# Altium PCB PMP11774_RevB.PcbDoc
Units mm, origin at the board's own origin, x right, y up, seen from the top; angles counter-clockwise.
Board outline 103.13 x 27 mm, 2 copper layers (Top Layer, Bottom Layer), stack 1.575 mm thick; 49 components, 22 nets, 113 pads, 0 vias.
Unrouted connection lines stored in the file: 1.
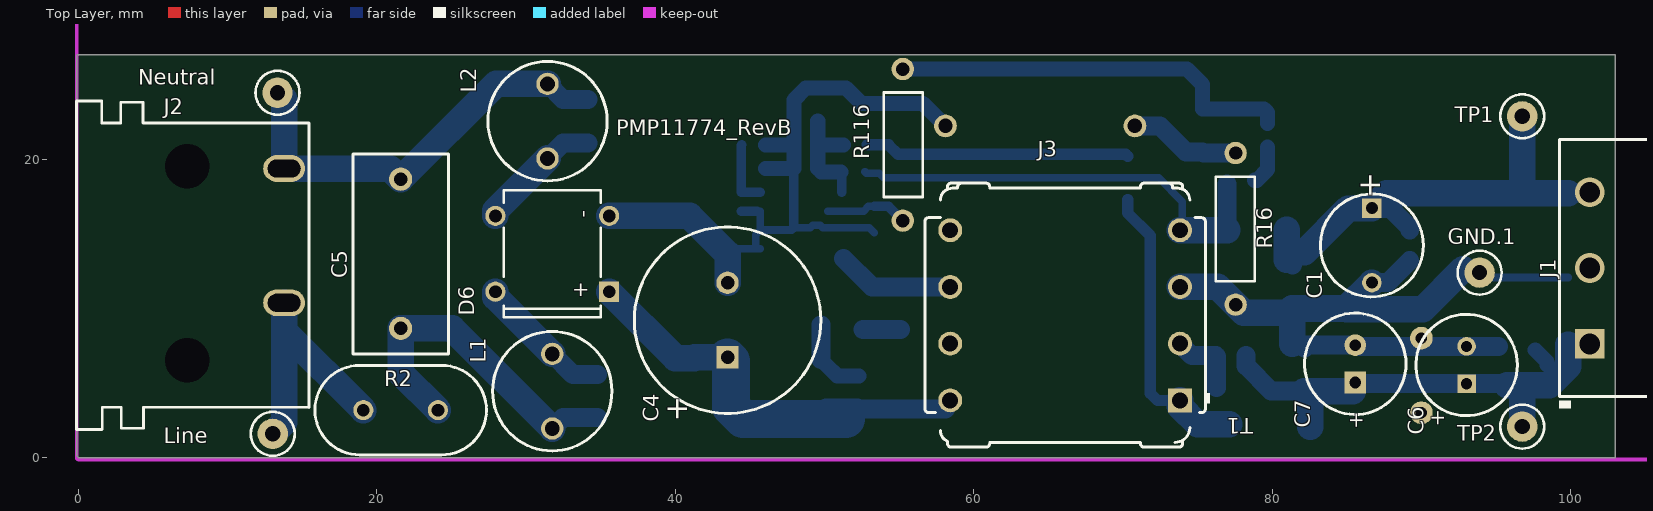
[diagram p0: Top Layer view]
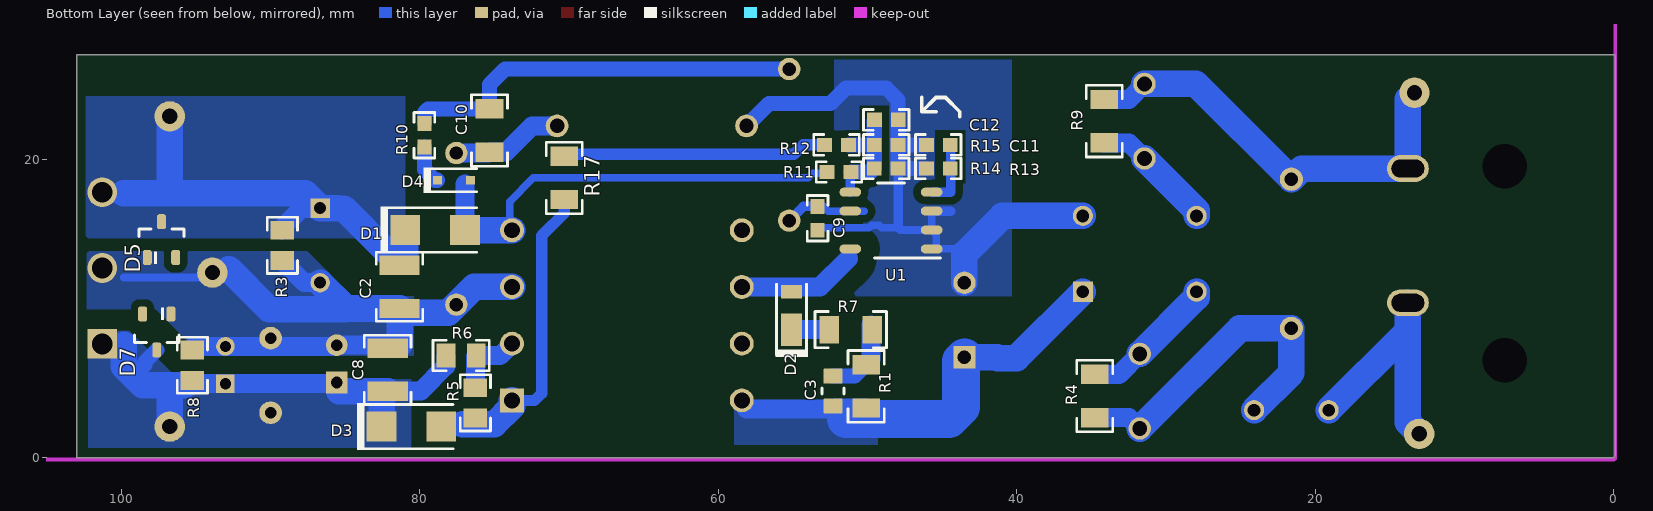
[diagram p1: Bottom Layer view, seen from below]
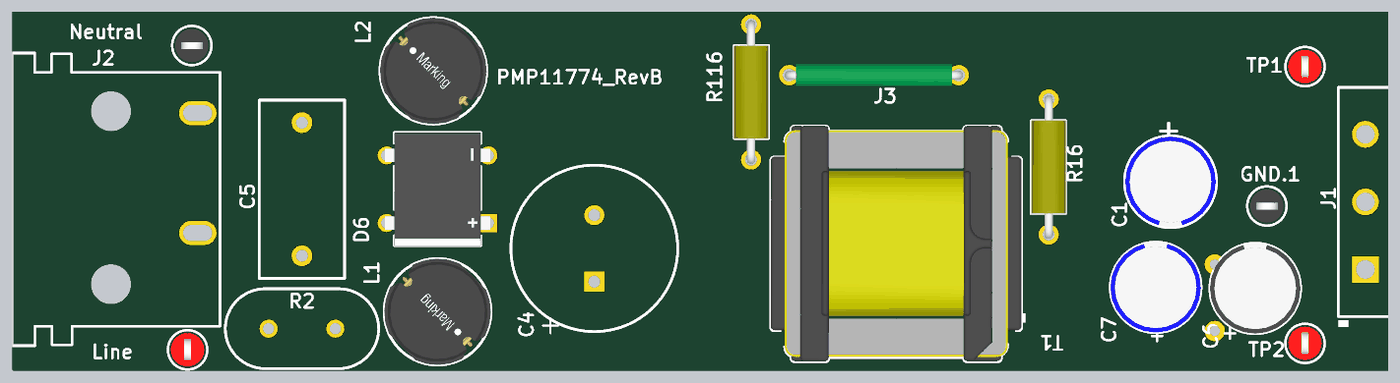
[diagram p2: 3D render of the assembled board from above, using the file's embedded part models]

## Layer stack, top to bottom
Top Solder: solder mask 0.0102, Solder Resist, Dk 3.5
Top Layer: signal copper 0.0356
Dielectric1: core 1.5037, FR-4, Dk 4.8
Bottom Layer: signal copper 0.0356
Bottom Solder: solder mask 0.0102, Solder Resist, Dk 3.5

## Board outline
0,0 -0.127,0.127 -0.127,27 103,27 103,0

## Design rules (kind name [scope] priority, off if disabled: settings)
AcuteAngle [All] p1: minimum=4.50000000000000E+0001 checktracksonly=FALSE
AssemblyTestPointUsage [All] p1: valid=2
Clearance "Schematic Clearance Constraint_1" [InNet('NetD2_2')] p1: gap=0.864
Clearance "Schematic Clearance Constraint" [InNet('VBULK')] p2: gap=0.838
Clearance Clearance_Keepouts [((IsTrack Or IsArc) And Not InPoly) And IsFree and IsKeepOut vs ((IsTrack Or IsArc) And Not InPoly) And IsFree and IsKeepOut] p3: gap=0
Clearance Clearance_BoardEdge_MountingHoles [OnCopper and InComponentClass('Mounting Holes') vs IsKeepOut] p4: gap=0.508
Clearance Clearance_BoardEdge_Poly [OnCopper and InPoly vs IsKeepOut] p5: gap=0.635
Clearance Clearance_BoardEdge [OnCopper and Not InComponentClass('Logo') and not InComponentClass('FiducialMark') and not InRegion(1000,500,4000,800) and Not IsKeepout vs IsKeepOut] p6: gap=0.508
Clearance Clearance_Poly [InPolygon] p7: gap=0.5
Clearance [All] p8: gap=0.508
ComponentClearance ComponentClearance_MountingHoles_FiducialMarks [InComponentClass('Mounting Holes') vs InComponentClass('FiducialMark')] p1: gap=1.27 collisioncheckmode=3 verticalgap=0.254 showdistances=FALSE
ComponentClearance ComponentClearance_Shunt [InComponentClass('Header') vs InComponentClass('Shunt')] p2: gap=0 collisioncheckmode=3 verticalgap=0 showdistances=FALSE
ComponentClearance ComponentClearance_Logo [InComponentClass('Logo')] p3: gap=1.27 collisioncheckmode=3 verticalgap=0.254 showdistances=FALSE
ComponentClearance ComponentClearance_ScrewToNut [(HasFootprint('NY PMS 440 0025 PH')) vs (HasFootprint('Keystone_1902C'))] p4: gap=0.127 collisioncheckmode=3 verticalgap=0.254 showdistances=FALSE
ComponentClearance ComponentClearance_MountingHoles [InComponentClass('Mounting Holes')] p5: gap=2.54 collisioncheckmode=3 verticalgap=2540 showdistances=FALSE
ComponentClearance ComponentClearance_SmallPassives [HasFootprint('0201*') or HasFootprint('0402*') or HasFootprint('0508') or HasFootprint('0603*') or HasFootprint('0612') or HasFootprint('0805*') or HasFootprint('0815*') or HasFootprint('0830*') or HasFootprint('1206*') or HasFootprint('1210*') or HasFootprint('1808*') or HasFootprint('1812*') or HasFootprint('1825*') or HasFootprint('2010*') or HasFootprint('2220*') or HasFootprint('2225*') or HasFootprint('2512*') or HasFootprint('2728*') or HasFootprint('3518*') vs HasFootprint('0201*') or HasFootprint('0402*') or HasFootprint('0508') or HasFootprint('0603*') or HasFootprint('0612') or HasFootprint('0805*') or HasFootprint('0815*') or HasFootprint('0830*') or HasFootprint('1206*') or HasFootprint('1210*') or HasFootprint('1808*') or HasFootprint('1812*') or HasFootprint('1825*') or HasFootprint('2010*') or HasFootprint('2220*') or HasFootprint('2225*') or HasFootprint('2512*') or HasFootprint('2728*') or HasFootprint('3518*')] p6: gap=0.508 collisioncheckmode=3 verticalgap=0.254 showdistances=FALSE
ComponentClearance ComponentClearance_THtoSMT [IsThruComponent vs IsSMTComponent] p7: gap=0.508 collisioncheckmode=3 verticalgap=0.762 showdistances=FALSE
ComponentClearance ComponentClearance_SMTtoSMT [IsSMTComponent vs IsSMTComponent] p8: gap=0.254 collisioncheckmode=3 verticalgap=0.762 showdistances=FALSE
ComponentClearance ComponentClearance_THtoTH [IsThruComponent vs IsThruComponent] p9: gap=0.508 collisioncheckmode=3 verticalgap=0.762 showdistances=FALSE
ComponentClearance [All] p10: gap=0.508 collisioncheckmode=3 verticalgap=0.254 showdistances=FALSE
DiffPairsRouting [All] p1: maxlimit=2.54 minlimit=0.254 mostfreqgap=0.254 toplayer_minwidth=0.381 toplayer_maxwidth=0.381 toplayer_prefwidth=0.381 bottomlayer_minwidth=0.381 bottomlayer_maxwidth=0.381 bottomlayer_prefwidth=0.381 maxuncoupledlength=25.4
FabricationTestPointUsage TestPointUsage [All] p1: valid=2 allowmultiple=FALSE
FabricationTestpoint Testpoint [All] p1: side=3 testpointundercomponent=TRUE minsize=1.016 maxsize=2.54 preferedsize=1.524 minholesize=0 maxholesize=1.016 preferedholesize=0.813 testpointgrid=0.025 allowsidetop=TRUE allowsidebottom=TRUE usegrid=TRUE gridtolerance=0
FanoutControl Fanout_LCC [IsLCC] p1: bgadir=Out bgaviamode=Centered fanoutstyle=Auto fanoutdirection=Alternating viagrid=0.025 // Fanout_LCC (Default Rule)
FanoutControl Fanout_BGA [IsBGA] p2: bgadir=Out bgaviamode=Centered fanoutstyle=Auto fanoutdirection=Alternating viagrid=0.025 // Fanout_BGA (Default Rule)
FanoutControl Fanout_Default [All] p4: bgadir=Out bgaviamode=Centered fanoutstyle=Auto fanoutdirection=Alternating viagrid=0.025 // Fanout_Default (Default Rule)
FanoutControl Fanout_Small [(CompPinCount < 5)] p5: bgadir=Out bgaviamode=Centered fanoutstyle=Auto fanoutdirection=OutThenIn viagrid=0.025 // Fanout_Small (Default Rule)
HoleSize [All] p1: absolutevalues=TRUE maxlimit=7 minlimit=0.3 maxpercent=80.000 minpercent=20.000
MinimumAnnularRing MinimumAnnularRing_ThermalPadVias [IsVia and InAnyComponent] p1: minimumring=0.15
MinimumAnnularRing [All] p2: minimumring=0.229
MinimumSolderMaskSliver MinimumSolderMaskSliver_Logo [InComponentClass('Logo') vs InComponentClass('Logo')] p1: minsoldermaskwidth=0.018
MinimumSolderMaskSliver [All] p2: minsoldermaskwidth=0.1
PlaneConnect [All] p1: planeconnectstyle=Relief reliefexpansion=0.254 reliefentries=4 reliefconductorwidth=0.254 reliefairgap=0.254
PolygonConnect [All] p1: connectstyle=Direct reliefconductorwidth=0.254 reliefentries=4 polygonreliefangle="90 Angle" airgapwidth=0.254
RoutingVias ThermalPadVias [IsVia and InAnyComponent] p1: holewidth=0.3 width=0.7 viastyle="Through Hole" minholewidth=0.3 minwidth=0.5 maxholewidth=0.5 maxwidth=1
RoutingVias [All] p2: holewidth=0.5 width=0.7 viastyle="Through Hole" minholewidth=0.3 minwidth=0.7 maxholewidth=1.016 maxwidth=1.651
SilkToBoardRegionClearance [Not ((IsComment or IsDesignator) And (Hide <> 'False')) and not InRegion(1000,500,4000,800)] p1:
SilkToSilkClearance SilkToSilkClearance_Pb-FreeLogo [(HasFootprint('Pb-Free_Overlay_Medium') OR HasFootprint('Pb-Free_Overlay_Small')) vs (HasFootprint('Pb-Free_Overlay_Medium') OR HasFootprint('Pb-Free_Overlay_Small'))] p1 off: silktosilkclearance=0
SilkToSilkClearance [All] p2 off: silktosilkclearance=0.127
SilkToSolderMaskClearance "Silk to Solder Mask Opening" [All] p1 off: minsilkscreentomaskgap=0.025 clearancetoexposedcopper=FALSE
SolderMaskExpansion [All] p1: expansion=0.05
UnpouredPolygon [All] p1: allowunpoured=FALSE
Width [All] p1: maxlimit=2.54 minlimit=0.152 preferedwidth=0.254 checkconnectedcopper=TRUE
14 further rules are at their usual default settings.

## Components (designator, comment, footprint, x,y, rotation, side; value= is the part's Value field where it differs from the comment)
C1 "EEU-FR1E151B" FR_630x1120 86.679,14.216 r270 top
C2 "GRM32ER71H106KA12L" 1210 81.361,11.438 r270 bottom
C3 "QMK212B7102KD-T" 0805_HV1 52.31,4.453 r270 bottom
C4 "EEUED2G150" CAPPR5-12.5X20 43.497,9.207 r90 top
C5 "R46KF310050P0K" R46_1300x1200x600 21.59,13.652 r90 top
C6 "10ZLH330MEFC6.3X11" ZLH_630x1100 93.029,6.199 r90 top
C7 "EEU-FM1E101" FM_630x1120 85.568,6.278 r90 top
C8 "GRM32ER71H106KA12L" 1210 82.155,5.881 r90 bottom
C9 "06035C104KAT2A" 0603 53.34,16.034 r270 bottom
C10 "UKL1E150MDD1TD" 1206 75.329,21.915 r270 bottom
C11 "06035A100JAT2A" 0603 45.25,20.955 r180 bottom
C12 "06035A100JAT2A" 0603 48.736,22.632 r0 bottom
D1 "STPS1150A" SMA 78.98,15.248 r180 bottom
D2 "DFLR1600-7" powerDI123 55.086,9.842 r90 bottom
D3 "B160-13-F" SMA 80.567,2.071 r180 bottom
D4 "BAV20WS-TP" sod-323 77.71,18.581 r180 bottom
D5 "DNP" SOT-23 97.314,14.605 r90 bottom
D6 "DF06M" DIOB_DFM 31.75,13.652 r180 top
D7 "DNP" SOT-23 97.631,8.414 r270 bottom
GND.1 "5001" Keystone5001 93.902,12.39 r90 top
J1 "1757255" TE_1757255 101.282,12.7 r90 top
J2 "770W-X2/10" CONN_AC_770W-SERIES 10.477,13.018 r90 top
J3 "923345-05-C" 923345-05-C 64.453,22.225 r0 top
L1 "744743102" WE-TI_8012 31.75,4.445 r90 top
L2 "744743102" WE-TI_8012 31.432,22.543 r270 top
Line "5000" Keystone5000 13.018,1.587 r0 top
Neutral "5001" Keystone5001 13.335,24.447 r90 top
R1 "RC1206FR-07120KL" 1206 50.087,4.77 r90 bottom
R2 "B57236S0100M000" THERM_B57236S0 21.59,3.175 r0 top
R3 "CRCW080510K0JNEA" 0805_HV 89.219,14.216 r90 bottom
R4 "RC1206FR-0710KL" 1206 34.766,4.127 r90 bottom
R5 "CRCW08050000Z0EA" 0805_HV 76.281,3.659 r90 bottom
R6 "CRCW08050000Z0EA" 0805_HV 77.234,6.834 r180 bottom
R7 "CRCW120610R0JNEA" 1206 51.117,8.572 r180 bottom
R8 "CRCW080510K0JNEA" 0805_HV 95.25,6.191 r270 bottom
R9 "RC1206FR-0710KL" 1206 34.131,22.543 r270 bottom
R10 "CRCW060310R0JNEAHP" 0603 79.694,21.598 r90 bottom
R11 "CRCW0603110KFKEA" 0603 51.911,19.14 r0 bottom
R12 "CRCW0603110KFKEA" 0603 52.07,20.955 r0 bottom
R13 "RT0603BRD071K38L" 0603 45.25,19.367 r180 bottom
R14 "CRCW060391K0JNEA" 0603 48.743,19.367 r0 bottom
R15 "RC0603FR-0747KL" 0603 48.743,20.955 r0 bottom
R16 "" RES_TH_CF14 77.551,15.327 r90 top
R17 "CRCW12060000Z0EA" 1206 70.314,18.74 r270 bottom
R116 "" RES_TH_CF14 55.245,20.955 r270 top
T1 "1P2S_EE1685_V2" Wurth_070-5420 66.121,9.533 r180 top
TP1 "5000" Keystone5000 96.76,22.868 r0 top
TP2 "5000" Keystone5000 96.76,2.071 r0 top
U1 "UCC28911DR" D0007A_N 48.425,15.883 r0 bottom

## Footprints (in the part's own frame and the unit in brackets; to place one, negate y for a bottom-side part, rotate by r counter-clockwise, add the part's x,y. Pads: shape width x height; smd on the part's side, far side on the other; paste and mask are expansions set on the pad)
0603 [mm] "0603 from SM-752 data"
  rect 1x0.95 smd: 1(-0.8,0) 2(0.8,0)
  silkscreen extent -1.52,-0.69 1.52,0.69, body extent -0.87,-0.47 0.87,0.47, height 1
0805_HV [mil] "0805 with 30mil clearance between pads"
  rect 50x63 smd: 1(-40,0) 2(40,0)
  silkscreen extent -74,-40 74,40, body extent -43,-29 43,29, height 57
0805_HV1 [mm] "Custom footprint based on analyzing multiple manufacturer recommendations"
  rrect10% 1x1.25 smd: 1(-1,0) 2(1,0)
  silkscreen extent -0.2,-0.75 0.2,0.75, body extent -1.1,-0.72 1.1,0.73, height 1.45
1206 [mm] "1206 from SM-752 data"
  rect 1.3x1.85 smd: 1(-1.45,0) 2(1.45,0)
  silkscreen extent -2.4,-1.21 2.4,1.21, body extent -1.7,-0.9 1.7,0.9, height 1.35
1210 [mm] "1210 from SM-752 data"
  rect 1.3x2.7 smd: 1(-1.45,0) 2(1.45,0)
  silkscreen extent -2.32,-1.57 2.32,1.57, body extent -1.7,-1.35 1.7,1.35, height 1.35
923345-05-C [mil] "Wire Jumper 500mil"
  round 60 hole 38: 1(-250,0) 2(250,0)
  body extent -263,-33 263,33, height 71
CAPPR5-12.5X20 [mm] "Capacitor, Electrolytic, Radial; Body 12.5 x 20 mm (Dia.xH typ); Pin Spacing 5 mm (typ)"
  rect 1.5x1.5 hole 0.9: 1(-2.5,0)
  round 1.5 hole 0.9: 2(2.5,0)
  silkscreen extent -6.25,-6.25 6.25,6.25, body extent -6.01,-6.01 6.01,6.01, height 22
CONN_AC_770W-SERIES [mm] "Qualtek Electronics"
  oval 1.8x2.8 hole 1.2 slot 2.2 at 90 deg: 1(6.35,-3.3) 2(-2.65,-3.3)
  round 2 hole 3 unplated: MH1(6.5,3.2) MH2(-6.5,3.2)
  silkscreen extent -11.12,-4.97 10.87,10.63, body extent -11.05,-4.8 10.8,10.6, height 22
D0007A_N [mm] "SOIC, 7-Leads, Body 4.9x3.9mm, Pitch 1.27mm, IPC Medium Density"
  oval 1.45x0.6 smd: 1(-2.725,1.905) 2(-2.725,0.635) 3(-2.725,-0.635) 4(-2.725,-1.905) 5(2.725,-1.905) 6(2.725,-0.635) 8(2.725,1.905)
  silkscreen extent -3.32,-2.5 1.1,2.52, body extent -3.01,-2.45 3.01,2.45, height 1.75
DIOB_DFM [mm] "Diodes Inc DFM package"
  rect 1.35x1.35 hole 0.85: 1(-3.81,2.54)
  round 1.35 hole 0.85: 2(-3.81,-2.54) 3(3.81,-2.54) 4(3.81,2.54)
  silkscreen extent -3.25,-4.27 3.25,4.24, body extent -3.93,-4.25 3.93,4.26, height 4.68
FM_630x1120 [mm] "PANASONIC"
  rect 1.45x1.45 hole 0.787: 1(-1.25,0)
  round 1.45 hole 0.787: 2(1.25,0)
  silkscreen extent -3.4,-3.4 3.4,3.4, body extent -3.37,-3.39 3.4,3.39, height 12.71
FR_630x1120 [mm] "TH, 2-Leads, Dia 6.3mm, Lead Spacing 2.5mm"
  rect 1.3x1.3 hole 0.8: 1(-2.5,0)
  round 1.3 hole 0.8: 2(2.5,0)
  silkscreen extent -3.45,-3.45 3.45,3.45, body extent -3.37,-3.39 3.4,3.39, height 15.21
Keystone5000 [mil] "For Keystone 500x miniature loop terminals"
  round 80 hole 40: 1(0,0)
  silkscreen extent -58,-58 58,58, body extent -49,-49 49,49, height 182
Keystone5001 [mil] "For Keystone 500x miniature loop terminals"
  round 80 hole 40: 1(0,0)
  silkscreen extent -58,-58 58,58, body extent -49,-49 49,49, height 182
powerDI123 [mm] "Diodes Inc recommended land pattern, document number DS30628 Rev. 6-2"
  rect 2.2x1.4 smd: 1(-1.275,0)
  rect 0.9x1.4 smd: 2(1.275,0)
  silkscreen extent -3.1,-1.09 1.76,1.09, body extent -2.37,-0.96 1.53,0.97, height 1
R46_1300x1200x600 [mm] "KEMET"
  round 1.55 hole 0.9: 1(-5,0) 2(5,0)
  silkscreen extent -6.7,-3.2 6.7,3.2, body extent -6.6,-3.1 6.6,3.1, height 12.1
RES_TH_CF14 [mm] "Stackpole 1/4W"
  round 1.5 hole 0.9: 1(-5.08,0) 2(5.08,0)
  silkscreen extent -3.51,-1.27 3.49,1.33, body extent -5.39,-1.29 5.39,1.29, height 2.6
SMA [mm] "Molded Diode, 2-Leads, Body 4.3x2.6mm, IPC Medium Density, based on OnSemi component dimensions and land pattern"
  rect 2x2 smd: 1(-2,0) 2(2,0)
  silkscreen extent -3.66,-1.57 2.79,1.57, body extent -2.6,-1.3 2.6,1.3, height 2.42
sod-323 [mm] "NXP recommended land pattern"
  rect 0.6x0.6 smd paste-0.05: 1(-1.1,0) 2(1.1,0)
  silkscreen extent -2.06,-0.86 1.53,0.86, body extent -1.3,-0.67 1.3,0.68, height 1.1
SOT-23 [mm] "SOT23, 3-Leads, Body 2.9x1.3mm, Pitch 0.95mm, Lead Span 2.5mm, IPC Medium Density"
  rrect50% 1x0.6 smd: 1(-1.2,0.95) 2(-1.2,-0.95) 3(1.2,0)
  silkscreen extent -1.63,-1.5 0.7,1.5, body extent -1.16,-1.45 1.21,1.45, height 1
TE_1757255 [mm] "TERM BLOCK 3x1, 5.08mm, TH"
  rect 2x2 hole 1.4: 1(-5.08,0)
  round 2 hole 1.4: 2(0,0) 3(5.08,0)
  silkscreen extent -9.4,-10.02 8.62,2.03, body extent -8.67,-10 8.57,2.05, height 8.6
THERM_B57236S0 [mm] "EPCOS"
  round 1.35 hole 0.85: 1(-2.5,0) 2(2.5,0)
  silkscreen extent -5.75,-3 5.75,3, body extent -5.75,-3 5.7,3, height 15.99
WE-TI_8012 [mm] "Radial Leaded, 2-Leads, Dia 8mm, Height 12.5mm, Pin Spacing 5mm"
  round 1.5 hole 1: 1(-2.5,0) 2(2.5,0)
  silkscreen extent -4,-4 4,4, body extent -5.35,-5.35 5.35,5.35, height 12.5
Wurth_070-5420 [mm] "TH, 8-Leads, Body 20.3x17.96mm, Pitch 3.8mm"
  rect 1.6x1.6 hole 1.07: 1(-7.7,5.7)
  round 1.6 hole 1.07: 2(-7.7,1.9) 3(-7.7,-1.9) 4(-7.7,-5.7) 5(7.7,-5.7) 6(7.7,-1.9) 7(7.7,1.9) 8(7.7,5.7)
  silkscreen extent -9.7,-8.86 9.4,8.84, body extent -9.4,-8.9 9.4,8.8, height 13.59
ZLH_630x1100 [mm] "Radial Leaded, 2-Leads, Dia 6.3mm, Height 11mm, Pin Spacing 2.5mm"
  rect 1.25x1.25 hole 0.75: 1(-1.25,0)
  round 1.25 hole 0.75: 2(1.25,0)
  silkscreen extent -3.4,-3.4 3.4,3.4, body extent -3.37,-3.39 3.4,3.39, height 12.51

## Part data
C1: "CAP, AL, 150 µF, 25 V, +/- 20%,  ohm, TH"
C2 C8: "CAP, CERM, 10uF, 50V, +/-10%, X7R, 1210"
C3: "CAP, CERM, 1000 pF, 250 V, +/- 10%, X7R, 0805"
C4: "CAP, AL, 15 µF, 400 V, +/- 20%, 1.909859 ohm, TH"
C5: "CAP, Film, 0.1 µF, 560 V, +/- 10%, TH"
C6: "CAP, AL, 330 µF, 10 V, +/- 20%, 0.094 ohm, TH"
C7: "CAP, AL, 100 µF, 25 V, +/- 20%, 0.13 ohm, TH"
C9: "CAP, CERM, 0.1uF, 50V, +/-10%, X7R, 0603"
C10: library part Capacitor, "TDK - CGA5L1X7R1E106M160AE - CAP, MLCC, X7R, 10UF, 25V, 1206"
C11: "CAP, CERM, 10 pF, 50 V, +/- 5%, C0G/NP0, 0603"
C12: "CAP, CERM, 10pF, 50V, +/-5%, C0G/NP0, 0603"
D1: library part STPS130A, "Diode, Schottky, 150V, 1A, SMA"
D2: "Diode, Standard Recovery Rectifier, 600 V, 1 A, PowerDI123"
D3: "Diode, Schottky, 60 V, 1 A, SMA"
D4: "Diode, P-N, 150 V, 0.2 A, SOD-323"
D5: library part BZX84C24LT1G, "Diode, Zener, 24 V, 225 mW, SOT-23"
D6: "Diode, Switching-Bridge, 600 V, 1 A, TH"
D7: library part BZX84C7V5LT1G, "Diode, Zener, 7.5 V, 225 mW, SOT-23"
GND.1 Neutral: "Test Point, TH, Miniature, Black"
J1: "Terminal Block, 5.08mm, 3x1, TH"
J2: "AC Receptacle, 2.5A, R/A, TH"
J3: "Jumper Wire, 500mil spacing, Green, pkg of 200"
L1 L2: "Inductor, Wirewound, Ferrite, 1 mH, 0.42 A, 2.2 ohm, TH"
Line TP1 TP2: "Test Point, TH, Miniature, Red"
R1: "RES, 120 k, 1%, 0.25 W, 1206"
R2: "Thermistor NTC, 10 ohm, 20%, Disc_11.5mmx6mm"
R3 R8: "RES, 10 k, 5%, 0.125 W, 0805"
R4 R9: "RES, 10.0 k, 1%, 0.25 W, 1206"
R5 R6: "RES, 0, 5%, 0.125 W, 0805"
R7: "RES, 10, 5%, 0.25 W, 1206"
R10: "RES, 10, 5%, 0.25 W, 0603"
R11 R12: "RES, 110 k, 1%, 0.1 W, 0603"
R13: "RES, 1.38 k, 0.1%, 0.1 W, 0603"
R14: "RES, 91 k, 5%, 0.1 W, 0603"
R15: "RES, 47.0 k, 1%, 0.1 W, 0603"
R16 R116: library part CF14JT47R0, "RES, 47, 5%, 0.25 W, Axial"
R17: "RES, 0, 5%, 0.25 W, 1206"
T1: library part 1P2S_EE1685, "Transformer, TH"
U1: "High Voltage Flyback Switcher with Primary-side Regulation and Constant-Current Control, D0007A"

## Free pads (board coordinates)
  round 1.524 hole 0.762: 0(90,8) 1(90,3)

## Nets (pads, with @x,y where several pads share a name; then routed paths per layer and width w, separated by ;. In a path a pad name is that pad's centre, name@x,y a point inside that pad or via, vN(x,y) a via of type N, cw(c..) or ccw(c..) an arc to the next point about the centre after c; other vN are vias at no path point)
-VPRI: C4.2 C9.2 C11.1 C12.1 D6.2 J3.1 R13.1 R14.1 R15.1 U1.1 U1.2 U1.3 | length 48.4
  Bottom Layer w0.508: 43.823,13.978 U1.1@45.395,13.978 ; U1.1 U1.1@45.395,13.978 ; U1.3 U1.2 ; C9.2@53.34,15.075 53.002,15.413 49.865,15.413 49.721,15.557 49.212,15.557 49.047,15.392 47.942,15.392 47.798,15.248 U1.2 ; U1.1@45.395,13.978 45.395,14.942 U1.2
  Bottom Layer w0.635: 44.43,16.51 U1.3@45.471,16.51 ; 47.942,15.392 R14.1
  Bottom Layer w1.016: R13.1 R14.1 R15.1 ; C11.1 R15.1 ; J3.1 56.604,23.724 52.476,23.724 51.435,24.765 48.736,24.765 47.942,23.971 R15.1
  Bottom Layer w1.778: D6.2 40.957,16.192 43.497,13.652 C4.2
GND: C1.2 C2.2 C6.2 C7.2 C8.2 C10.2 D5.1 D7.1 GND.1.1 J1.2 J3.2 pad.0 R3.1 R8.1 R16.1 R16.2 T1.3 | length 56.5
  Bottom Layer w0.508: 92.789,12.065 99.854,12.065
  Bottom Layer w1.27: J3.2@70.81,22.233 72.471,22.233 74.239,20.465 C10.2 ; C10.2@75.387,20.407 R16.2 ; C8.2 82.352,7.528 C7.2 85.647,7.449 C6.2 R8.1@95.177,7.449 ; C1.2 87.735,11.716 R3.1
  Bottom Layer w1.778: T1.3 76.366,11.432 R16.1 78.107,9.691 81.065,9.691 C2.2 ; C8.2@81.361,7.628 C2.2 ; C1.2 84.951,9.988 ; 92.791,12.628 90.092,9.929 85.009,9.929 84.951,9.988 ; C2.2 84.951,9.988
NetC3_1: C3.1 R1.2 R7.2 | length 5.4
  Bottom Layer w1.016: R1.2@49.749,6.559 R1.2 50.855,5.453 C3.1
  Bottom Layer w1.27: R1.2@49.749,6.559 R7.2@49.749,8.898
NetC5_1: C5.1 L1.1 R2.2 R4.1 | length 22.8
  Bottom Layer w1.27: L1.1 32.483,2.678 R4.1
  Bottom Layer w1.778: R2.2 21.59,5.675 C5.1 25.043,8.652 L1.1
NetC5_2: C5.2 J2.1 L2.1 Neutral.1 R9.1 | length 29
  Bottom Layer w1.27: L2.1 32.483,23.992 R9.1
  Bottom Layer w1.778: Neutral.1 13.777,24.005 J2.1 20.875,19.368 C5.2 27.98,25.043 L2.1
NetC9_1: C9.1 R116.2 U1.6 | length 5.6
  Bottom Layer w0.508: 50.205,16.51 52.615,16.51 52.939,16.834 C9.1
  Bottom Layer w0.635: C9.1 54.286,16.834 R116.2
NetC10_1: C10.1 R10.2 R116.1 | length 27.3
  Bottom Layer w1.016: R116.1 74.295,26.035 75.329,25.001 C10.1 79.449,23.365 79.694,23.119 R10.2
NetC11_2: C11.2 R13.2 U1.4 | length 4.4
  Bottom Layer w0.635: 44.43,17.78 44.43,20.935 C11.2 ; 44.438,17.788 U1.4
NetC12_2: C12.2 R11.1 R12.1 R14.2 R15.2 U1.5 | length 7.9
  Bottom Layer w0.635: R14.2 R14.2@49.77,19.14 ; U1.5 R11.1@51.15,19.101
  Bottom Layer w1.016: R14.2 R15.2 ; C12.2@49.542,22.543 R15.2 ; R14.2@49.77,19.14 R11.1 ; R12.1 R15.2
NetD2_1: D2.1 R7.1 | length 2.5
  Bottom Layer w1.27: R7.1 52.572,8.568 D2.1
NetD2_2: D2.2 T1.6 U1.8 | length 7.9
  Bottom Layer w1.27: 51.276,13.335 53.179,11.432 T1.6
NetD4_1: D4.1 R10.1 | length 2.7
  Bottom Layer w1.016: D4.1 78.98,18.581 79.694,19.296 R10.1
NetD6_3: D6.3 L2.2 R9.2 | length 8.4
  Bottom Layer w1.27: L2.2 32.483,21.093 R9.2
  Bottom Layer w1.778: D6.3 27.94,16.55 L2.2
NetD6_4: D6.4 L1.2 R4.2 | length 9.3
  Bottom Layer w1.27: L1.2 33.139,5.556 33.591,5.556 33.612,5.577 R4.2
  Bottom Layer w1.778: D6.4 27.94,10.755 L1.2
NetJ2_2: J2.2 Line.1 R2.1 | length 16.6
  Bottom Layer w1.778: Line.1 13.777,2.347 13.777,8.488 ; J2.2 13.777,8.488 ; R2.1 13.777,8.488
NetR5_2: R5.2 R6.2 T1.2 | length 4.9
  Bottom Layer w1.27: T1.2 74.62,6.834 R6.2 76.281,6.77 R5.2
NetR12_2: R12.2 R17.1 | length 17.8
  Bottom Layer w0.762: R12.2 54.292,20.955 54.92,20.328 70.176,20.328 R17.1
VBULK: C3.2 C4.1 D6.1 R1.1 T1.8 | length 29.1
  Bottom Layer w1.27: R1.1 C3.2@52.193,3.32 ; C3.2@52.389,3.262 T1.8@58.105,3.262
  Bottom Layer w1.778: D6.1 40.005,6.667 41.275,6.667 41.315,6.707 C4.1
  Bottom Layer w2.54: C4.1 43.737,6.468 43.737,3.386 44.531,2.592 51.437,2.592
VOUT_5: C6.1 C7.1 C8.1 D3.1 D7.3 J1.1 pad.1 R6.1 R8.2 TP2.1 | length 30.2
  Bottom Layer w1.016: D7.3 98.425,6.42 98.425,6.191
  Bottom Layer w1.27: R6.1 78.25,6.135 79.932,4.453 82.134,4.453 C8.1 ; C7.1@85.647,4.949 C6.1 R8.2@95.177,4.949
  Bottom Layer w1.778: C8.1 C7.1@85.409,4.453 ; D3.1 C8.1@82.567,4.019 ; R8.2@95.744,4.849 96.76,4.849 ; TP2.1 96.76,4.849 ; 99.856,7.548 99.856,6.119 98.586,4.849 96.76,4.849
VOUT_18: C1.1 C2.1 D1.1 D5.3 J1.3 R3.2 TP1.1 | length 30.4
  Bottom Layer w1.27: C2.1 80.98,13.269 81.499,13.788 ; C1.1 86.719,16.676 87.949,16.676 89.219,15.406 R3.2
  Bottom Layer w1.778: C2.1@80.98,13.269 D1.1 ; 82.155,13.754 85.083,16.682 ; 85.568,16.716 C1.1 87.672,17.708 99.856,17.708 ; 96.76,17.788 TP1.1
VSEC: D1.2 D4.2 R11.2 T1.4 | length 30.3
  Bottom Layer w0.508: R11.2 52.801,19.05 53.657,19.05 53.967,18.74 72.382,18.74 73.977,17.145 73.977,15.389 T1.4
  Bottom Layer w1.27: D1.2 76.98,18.339
  Bottom Layer w1.778: T1.4 76.965,15.232 D1.2
VSEC_5: D3.2 R5.1 R17.2 T1.1 | length 20
  Bottom Layer w0.762: R17.2 70.314,16.39 71.836,14.868 71.836,4.294 72.312,3.818 73.806,3.818 T1.1
  Bottom Layer w1.778: T1.1 73.821,3.42 75.011,2.23 77.139,2.23
pads on no net: D5.2 D7.2 J2.MH1 J2.MH2 T1.5 T1.7

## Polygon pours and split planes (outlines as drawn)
-VPRI on Bottom Layer "Bottom Layer-No Net 3" (solid, remove dead copper, pour order 12): 40.322,10.795 51.911,10.795 52.229,11.112 52.229,26.67 40.322,26.67
VBULK on Bottom Layer "Bottom Layer-No Net 6" (solid, remove dead copper, pour order 23): 49.294,3.818 49.373,3.738 58.921,3.738 58.921,0.716 58.898,0.692 58.789,0.801 49.294,0.801
VOUT_18 on Bottom Layer "Bottom Layer-No Net 2" (solid, remove dead copper, pour order 13): 80.964,24.217 80.964,14.692 102.237,14.692 102.396,14.851 102.396,24.217
VOUT_5 on Bottom Layer "Bottom Layer-No Net 1" (solid, remove dead copper, pour order 11): 80.567,5.246 96.204,5.246 99.459,8.501 99.697,8.501 102.316,8.501 102.237,8.421 102.237,0.643 80.625,0.643 80.567,0.585
GND on Bottom Layer "Bottom Layer-No Net" (solid, remove dead copper, pour order 7): 80.409,10.803 84.536,10.803 84.695,10.961 87.552,13.819 88.108,13.819 102.078,13.819 102.157,13.898 102.316,13.739 102.316,9.929 97.702,9.929 94.686,6.913 94.606,6.834 80.409,6.834

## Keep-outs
Keep-Out Layer:
  lines w0.254: -0.127,0 ccw(c0,0) 0,-0.127 ; -0.127,0 ccw(c0,0) 0,-0.127 ; -0.127,0 -0.127,87.63 ; -0.127,87.63 cw(c0,87.63) 0,87.757 ; -0.127,87.63 cw(c0,87.63) 0,87.757 ; 0,-0.127 125.73,-0.127 ; 0,87.757 125.73,87.757 ; 125.73,-0.127 ccw(c125.73,0) 125.857,0 ; 125.73,-0.127 ccw(c125.73,0) 125.857,0 ; 125.73,87.757 cw(c125.73,87.63) 125.857,87.63 ; 125.73,87.757 cw(c125.73,87.63) 125.857,87.63 ; 125.857,0 125.857,87.63
  text ".Layer_Name" at 14.656,-21.806 h1.52

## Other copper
Top Layer:
  text ".Layer_Name" at 14.656,-21.806 h1.52
Bottom Layer:
  text ".Layer_Name" at 14.656,-21.806 h1.52

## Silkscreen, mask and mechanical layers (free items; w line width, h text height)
Top Overlay:
  text "PMP11774_RevB" at 36.036,21.59 h1.02
  text ".Layer_Name" at 14.656,-21.806 h1.52
Bottom Overlay:
  lines w0.254: 43.815,22.86 43.815,23.177 44.767,24.13 45.402,24.13 46.355,23.177 ; 45.402,23.177 46.355,23.177 ; 46.355,23.177 46.355,24.13 46.355,23.177
  text ".Layer_Name" at 14.656,-21.806 h0.76
Top Paste:
  text ".Layer_Name" at 14.656,-21.806 h1.52
Bottom Paste:
  text ".Layer_Name" at 14.656,-21.806 h1.52
Top Solder:
  text ".Layer_Name" at 14.656,-21.806 h1.52
  text ".Layer_Name" at 14.656,-21.806 h1.52
Bottom Solder:
  text ".Layer_Name" at 14.656,-21.806 h1.52
Drill Guide:
  text ".Layer_Name" at 14.656,-21.806 h1.52
M1 Board Outline:
  the board outline again, w0.254
  text ".Layer_Name" at 14.656,-21.806 h1.52
M2 Board Dimensions:
  rectangle: 0,-6.985 3.175,-3.81
  rectangle: 3.175,-10.16 12.7,-6.985
  lines w0.178: 0,-6.985 25.4,-6.985 ; 3.175,-10.16 3.175,-3.81 ; 6.35,-10.16 6.35,-3.81 ; 12.7,-10.16 12.7,-3.81 ; 19.05,-10.16 19.05,-3.81 ; 0,-10.16 25.4,-10.16 25.4,-3.81 0,-3.81 0,-10.16
  text ".Layer_Name" at 14.656,-21.806 h1.52
M3 3D STEP Top:
  text ".Layer_Name" at 14.656,-21.806 h1.52
M4 3D STEP Bottom:
  text ".Layer_Name" at 14.656,-21.806 h1.52
M5 Assembly Top:
  lines w0.254: -7.417,-23.626 160.223,-23.626 ; -7.417,-18.462 160.274,-18.462 ; -7.417,-13.297 -7.417,-28.791 94.31,-28.791 160.274,-28.791 160.274,-13.297 -7.404,-13.297 -7.404,-28.791 32.614,-28.791 ; 55.194,-28.791 55.194,-13.297 ; 87.376,-18.462 87.376,-13.297 ; 108.712,-18.462 108.712,-13.297 ; 124.511,-28.956 124.511,-23.804
  text "PCB VIEWED FROM TOP SIDE" at -5.804,-16.654 h1.52
  text "BOARD #:" at 57.099,-16.654 h1.52
  text ".PRJ_Number" at 70.955,-16.654 h1.52
  text "REV:" at 92.405,-16.654 h1.52
  text ".PCB_Rev" at 99.809,-16.654 h1.52
  text "SVN REV:" at 113.69,-16.654 h1.52
  text ".VersionControl_RevNumber" at 126.543,-16.654 h1.52
  text "PLOT NAME =" at -5.804,-27.034 h1.52
  text ".plot_File_Name" at 14.656,-27.034 h1.52
  text "GENERATED    :" at 57.15,-27.034 h1.52
  text ".Print_Date" at 79.235,-27.034 h1.52
  text ".Print_Time" at 97.752,-27.034 h1.52
  text "TEXAS INSTRUMENTS" at 129.87,-27.034 h1.52
M6 Assembly Bottom:
  lines w0.254: -7.429,-18.474 160.261,-18.474 ; -7.379,-23.639 160.261,-23.639 ; 28.334,-28.969 28.334,-23.817 ; 44.133,-18.474 44.133,-13.31 ; 65.468,-18.474 65.468,-13.31 ; 97.65,-28.804 97.65,-13.31 ; 120.231,-28.804 160.249,-28.804 160.249,-13.31 -7.429,-13.31 -7.429,-28.804 58.534,-28.804 160.261,-28.804 160.261,-13.31
  text ".VersionControl_RevNumber" at 26.302,-16.667 h1.52
  text "SVN REV:" at 39.154,-16.667 h1.52
  text ".PCB_Rev" at 53.035,-16.667 h1.52
  text "REV:" at 60.439,-16.667 h1.52
  text ".PRJ_Number" at 81.89,-16.667 h1.52
  text "BOARD #:" at 95.745,-16.667 h1.52
  text "PCB VIEWED FROM BOTTOM SIDE" at 158.648,-16.667 h1.52
  text "TEXAS INSTRUMENTS" at 22.974,-27.047 h1.52
  text ".Print_Time" at 55.093,-27.047 h1.52
  text ".Print_Date" at 73.609,-27.047 h1.52
  text "GENERATED    :" at 95.694,-27.047 h1.52
  text ".plot_File_Name" at 138.189,-27.047 h1.52
  text "PLOT NAME =" at 158.648,-27.047 h1.52
M9 Title Sheet:
  drawing of 57 lines, arcs and shapes, not listed
  text "1" at 18.792,204.127 h1.78
  text "2" at 82.182,204.127 h1.78
  text "3" at 145.411,204.127 h1.78
  text "4" at 209.08,204.127 h1.78
  text "5" at 272.555,204.127 h1.78
  text "6" at 336.182,204.127 h1.78
  text "A" at -10.579,175.095 h1.78
  text "A" at 365.341,175.095 h1.78
  text "B" at -10.579,114.643 h1.78
  text "B" at 365.341,114.643 h1.78
  text "C" at -10.579,54.318 h1.78
  text "C" at 365.341,54.318 h1.78
  text "PROJECT TITLE:" at 288.125,7.048 h1.14
  text ".PRJ_Title" at 289.395,3.662 h1.78
  text "DESIGNED FOR:" at 288.125,-0.597 h1.14
  text ".PRJ_Customer" at 289.395,-4.153 h1.78
  text "D" at -10.579,-5.88 h1.78
  text "D" at 365.341,-5.88 h1.78
  text "FILE NAME:" at 288.125,-8.217 h1.14
  text ".PCB_File_Name_No_Path" at 289.395,-11.265 h1.78
  text "Texas Instruments (TI) and/or its licensors do not warrant the accuracy or completeness of this specification" at 161.9,-15.376 h1.14
  text "ENGINEER:" at 288.125,-15.583 h1.14
  text "LAYOUT BY:" at 326.352,-15.583 h1.14
  text "or any information contained therein. TI and/or its licensors do not warrant that this design will meet" at 160.757,-18.237 h1.14
  text ".PRJ_Engineer" at 289.395,-19.52 h1.78
  text ".PCB_Layout" at 327.635,-19.52 h1.78
  text "the specifications, will be suitable for your application or fit for any particular purpose, or will operate in" at 160.757,-21.099 h1.14
  text ".Layer_Name" at 14.656,-21.806 h1.52
  text "ALTIUM DESIGNER VERSION:" at 326.352,-23.457 h1.14
  text "an implementation. TI and/or its licensors do not warrant that the design is production worthy. You should" at 160.757,-23.961 h1.14
  text "completely validate and test your design implementation to confirm the system functionality for your application." at 161.9,-26.822 h1.14
  text ".print_Scale" at 289.395,-26.843 h1.78
  text ".Application_BuildNumber" at 327.635,-26.843 h1.78
  text "1" at 18.792,-32.093 h1.78
  text "2" at 82.182,-32.093 h1.78
  text "3" at 145.411,-32.093 h1.78
  text "4" at 209.08,-32.093 h1.78
  text "5" at 272.555,-32.093 h1.78
  text "6" at 336.182,-32.093 h1.78
M10 Fab Notes:
  text ".Layer_Name" at 14.656,-21.806 h1.52
M11 Gerber Information:
  lines w0.254: -7.417,-23.626 160.223,-23.626 ; -7.417,-18.462 160.274,-18.462 ; -7.417,-13.297 -7.417,-28.791 94.31,-28.791 160.274,-28.791 160.274,-13.297 -7.404,-13.297 -7.404,-28.791 32.614,-28.791 ; 55.194,-28.791 55.194,-13.297 ; 87.376,-18.462 87.376,-13.297 ; 108.712,-18.462 108.712,-13.297 ; 124.511,-28.956 124.511,-23.804
  text "ALL ARTWORK VIEWED FROM TOP SIDE" at -5.804,-16.654 h1.52
  text "BOARD #:" at 57.099,-16.654 h1.52
  text ".PRJ_Number" at 70.955,-16.654 h1.52
  text "REV:" at 92.405,-16.654 h1.52
  text ".PCB_Rev" at 99.809,-16.654 h1.52
  text "SVN REV:" at 113.69,-16.654 h1.52
  text ".VersionControl_RevNumber" at 126.543,-16.654 h1.52
  text "LAYER NAME =" at -5.804,-21.806 h1.52
  text "PLOT NAME =" at -5.804,-27.034 h1.52
  text ".plot_File_Name" at 14.656,-27.034 h1.52
  text "GENERATED    :" at 57.15,-27.034 h1.52
  text ".Print_Date" at 79.235,-27.034 h1.52
  text ".Print_Time" at 97.752,-27.034 h1.52
  text "TEXAS INSTRUMENTS" at 129.87,-27.034 h1.52
M12 Stackup:
  text ".Layer_Name" at 14.656,-21.806 h1.52
M13 Component Bodies Top:
  text ".Layer_Name" at 14.656,-21.806 h1.52
M14 Component Bodies Bottom:
  text ".Layer_Name" at 14.656,-21.806 h1.52
M15 Courtyards Top:
  text ".Layer_Name" at 14.656,-21.806 h1.52
M16 Courtyards Bottom:
  text ".Layer_Name" at 14.656,-21.806 h1.52
Drill Drawing:
  text ".Layer_Name" at 14.656,-21.806 h1.52

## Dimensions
0,-10.16 to 25.4,-10.16 on M2 Board Dimensions
0,0 to 103,27 on M2 Board Dimensions
0,0 to -0.127,0.127 on M2 Board Dimensions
